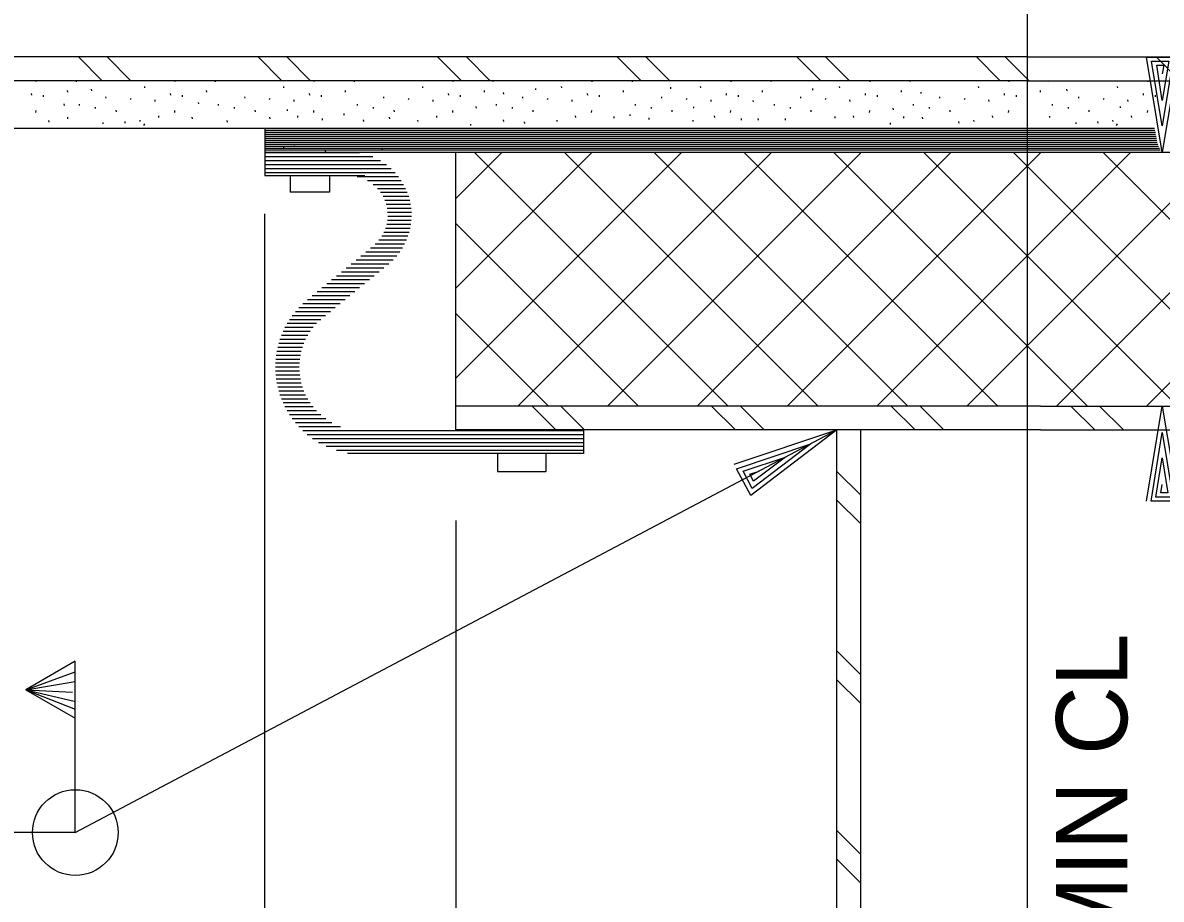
# Model space of a CAD drawing. Extents: x 22411.4 to 22495.4, y 22369.6 to 22415.
# Drawn here: x 22466.704 to 22469.692, y 22386.462 to 22388.762 of the extents above; entities that cross this region are included whole.
import ezdxf

# ---------------------------------------------------------------- set-up
doc = ezdxf.new("R2010")
doc.units = 0
for name, color, linetype in [('Level 1', 7, 'Continuous'), ('Level 10', 7, 'Continuous'), ('Level 2', 7, 'Continuous'), ('Level 4', 7, 'Continuous'), ('Level 8', 7, 'Continuous')]:
    doc.layers.add(name, color=color, linetype=linetype)

msp = doc.modelspace()

# ---------------------------------------------------------------- linework, layer by layer
at = {"layer": 'Level 1'}
for p, q in [((22469.3408, 22385.4019), (22469.3408, 22394.6266)), ((22467.4056, 22388.3603), (22467.4056, 22388.3173)), ((22467.5093, 22388.3603), (22467.5093, 22388.3173)), ((22467.5093, 22388.3173), (22467.4056, 22388.3173)), ((22467.3386, 22388.261), (22467.3386, 22385.4818)), ((22468.785, 22388.0689), (22468.785, 22388.0689)), ((22468.8753, 22387.6934), (22468.8753, 22387.6934)), ((22467.9496, 22387.6317), (22467.9496, 22387.5841)), ((22468.0771, 22387.6317), (22468.0771, 22387.5841)), ((22467.9496, 22387.5841), (22468.0771, 22387.5841)), ((22467.8408, 22387.4555), (22467.8408, 22385.4646))]:
    msp.add_line(p, q, dxfattribs=at)
for points in [[(22469.7359, 22388.6719), (22469.6946, 22388.4225), (22469.6533, 22388.6719), (22469.7239, 22388.6719), (22469.6946, 22388.4919), (22469.6666, 22388.6612), (22469.7119, 22388.6612), (22469.6946, 22388.5585), (22469.6799, 22388.6505), (22469.6986, 22388.6505), (22469.6946, 22388.6279)], [(22469.6533, 22387.5065), (22469.6946, 22387.7559), (22469.7359, 22387.5065), (22469.6653, 22387.5065), (22469.6946, 22387.6865), (22469.7226, 22387.5172), (22469.6773, 22387.5172), (22469.6946, 22387.6199), (22469.7093, 22387.5279), (22469.6906, 22387.5279), (22469.6946, 22387.5505)]]:
    msp.add_lwpolyline(points, dxfattribs=at)
at = {"layer": 'Level 10'}
for p, q in [((22466.8419, 22386.6366), (22468.8408, 22387.6934)), ((22468.8408, 22387.6934), (22468.8408, 22387.6934)), ((22468.7719, 22387.6569), (22468.7719, 22387.6569)), ((22466.8419, 22387.0866), (22466.7118, 22387.0116)), ((22466.8419, 22386.6366), (22466.8419, 22387.0866)), ((22466.7118, 22387.0116), (22466.8419, 22387.0584)), ((22466.7118, 22387.0116), (22466.8419, 22387.0329)), ((22466.7118, 22387.0116), (22466.8416, 22386.9366)), ((22466.7118, 22387.0116), (22466.8348, 22387.0051)), ((22466.7118, 22387.0116), (22466.8393, 22386.9819)), ((22466.7118, 22387.0116), (22466.8419, 22386.9609)), ((22466.8419, 22386.6366), (22465.3414, 22386.6366))]:
    msp.add_line(p, q, dxfattribs=at)
msp.add_lwpolyline([(22468.5711, 22387.6034), (22468.8408, 22387.6934), (22468.6146, 22387.5212), (22468.5774, 22387.5915), (22468.7719, 22387.6569), (22468.6182, 22387.54), (22468.5944, 22387.5851), (22468.7056, 22387.6219), (22468.6218, 22387.5589), (22468.612, 22387.5775), (22468.6366, 22387.5854)], dxfattribs=at)
msp.add_circle((22466.842, 22386.6365), 0.1125, dxfattribs=at)
at = {"layer": 'Level 2'}
for p, q in [((22469.3408, 22388.6725), (22464.1584, 22388.6725)), ((22469.3408, 22388.6725), (22474.5233, 22388.6725)), ((22469.3408, 22388.61), (22464.195, 22388.61)), ((22469.3408, 22388.61), (22474.4866, 22388.61)), ((22466.7276, 22388.572), (22466.7273, 22388.5761)), ((22466.7588, 22388.5679), (22466.7585, 22388.572)), ((22466.8219, 22388.5802), (22466.8216, 22388.5843)), ((22466.8849, 22388.5839), (22466.8846, 22388.5879)), ((22467.0244, 22388.591), (22467.0241, 22388.5951)), ((22467.0923, 22388.572), (22467.092, 22388.5761)), ((22467.1236, 22388.5679), (22467.1233, 22388.572)), ((22467.1867, 22388.5802), (22467.1863, 22388.5843)), ((22467.3892, 22388.591), (22467.3888, 22388.5951)), ((22467.4571, 22388.572), (22467.4568, 22388.5761)), ((22467.4883, 22388.5679), (22467.488, 22388.572)), ((22467.5514, 22388.5802), (22467.5511, 22388.5843)), ((22467.7539, 22388.591), (22467.7536, 22388.5951)), ((22467.8218, 22388.572), (22467.8215, 22388.5761)), ((22467.8531, 22388.5679), (22467.8528, 22388.572)), ((22467.9162, 22388.5802), (22467.9158, 22388.5843)), ((22467.9662, 22388.5747), (22467.9659, 22388.5788)), ((22468.0507, 22388.5857), (22468.0504, 22388.5898)), ((22468.1187, 22388.591), (22468.1183, 22388.5951)), ((22468.1866, 22388.572), (22468.1863, 22388.5761)), ((22468.2178, 22388.5679), (22468.2175, 22388.572)), ((22468.2809, 22388.5802), (22468.2806, 22388.5843)), ((22468.405, 22388.5891), (22468.4047, 22388.5932)), ((22468.4834, 22388.591), (22468.4831, 22388.5951)), ((22468.5513, 22388.572), (22468.551, 22388.5761)), ((22468.5826, 22388.5679), (22468.5823, 22388.572)), ((22468.6457, 22388.5802), (22468.6453, 22388.5843)), ((22468.7777, 22388.5854), (22468.7773, 22388.5895)), ((22468.8482, 22388.591), (22468.8478, 22388.5951)), ((22468.9161, 22388.572), (22468.9158, 22388.5761)), ((22468.9473, 22388.5679), (22468.947, 22388.572)), ((22469.0104, 22388.5802), (22469.0101, 22388.5843)), ((22469.0622, 22388.5763), (22469.0619, 22388.5803)), ((22469.2129, 22388.591), (22469.2126, 22388.5951)), ((22469.2808, 22388.572), (22469.2805, 22388.5761)), ((22469.3121, 22388.5679), (22469.3118, 22388.572)), ((22469.3752, 22388.5802), (22469.3748, 22388.5843)), ((22469.4447, 22388.5834), (22469.4444, 22388.5875)), ((22469.5777, 22388.591), (22469.5773, 22388.5951)), ((22469.6456, 22388.572), (22469.6453, 22388.5761)), ((22469.6768, 22388.5679), (22469.6765, 22388.572)), ((22466.8133, 22388.5453), (22466.813, 22388.5494)), ((22466.8532, 22388.5448), (22466.8528, 22388.5489)), ((22466.9225, 22388.5638), (22466.9222, 22388.5679)), ((22466.9871, 22388.5605), (22466.9889, 22388.5644)), ((22467.0516, 22388.5557), (22467.0513, 22388.5598)), ((22467.1658, 22388.549), (22467.1655, 22388.5531)), ((22467.2179, 22388.5448), (22467.2176, 22388.5489)), ((22467.2873, 22388.5638), (22467.2869, 22388.5679)), ((22467.3518, 22388.5605), (22467.3537, 22388.5644)), ((22467.4163, 22388.5557), (22467.416, 22388.5598)), ((22467.5827, 22388.5448), (22467.5823, 22388.5489)), ((22467.652, 22388.5638), (22467.6517, 22388.5679)), ((22467.7166, 22388.5605), (22467.7184, 22388.5644)), ((22467.7811, 22388.5557), (22467.7808, 22388.5598)), ((22467.8946, 22388.538), (22467.8943, 22388.542)), ((22467.9474, 22388.5448), (22467.9471, 22388.5489)), ((22468.0168, 22388.5638), (22468.0164, 22388.5679)), ((22468.0813, 22388.5605), (22468.0832, 22388.5644)), ((22468.1458, 22388.5557), (22468.1455, 22388.5598)), ((22468.3122, 22388.5448), (22468.3118, 22388.5489)), ((22468.3815, 22388.5638), (22468.3812, 22388.5679)), ((22468.4461, 22388.5605), (22468.4479, 22388.5644)), ((22468.4656, 22388.5377), (22468.4652, 22388.5418)), ((22468.5106, 22388.5557), (22468.5103, 22388.5598)), ((22468.6216, 22388.5542), (22468.6213, 22388.5583)), ((22468.6769, 22388.5448), (22468.6766, 22388.5489)), ((22468.7463, 22388.5638), (22468.7459, 22388.5679)), ((22468.8108, 22388.5605), (22468.8127, 22388.5644)), ((22468.8753, 22388.5557), (22468.875, 22388.5598)), ((22469.0417, 22388.5448), (22469.0413, 22388.5489)), ((22469.111, 22388.5638), (22469.1107, 22388.5679)), ((22469.1756, 22388.5605), (22469.1774, 22388.5644)), ((22469.2401, 22388.5557), (22469.2398, 22388.5598)), ((22469.4064, 22388.5448), (22469.4061, 22388.5489)), ((22469.4758, 22388.5638), (22469.4754, 22388.5679)), ((22469.5403, 22388.5605), (22469.5422, 22388.5644)), ((22469.5849, 22388.5386), (22469.5846, 22388.5427)), ((22469.6048, 22388.5557), (22469.6045, 22388.5598)), ((22466.738, 22388.5269), (22466.7388, 22388.5318)), ((22466.8225, 22388.5104), (22466.8222, 22388.5145)), ((22466.8953, 22388.5367), (22466.895, 22388.5408)), ((22466.9497, 22388.5285), (22466.9493, 22388.5326)), ((22467.0611, 22388.5136), (22467.0608, 22388.5177)), ((22467.1028, 22388.5269), (22467.1035, 22388.5318)), ((22467.1493, 22388.5104), (22467.1489, 22388.5145)), ((22467.2601, 22388.5367), (22467.2598, 22388.5408)), ((22467.3144, 22388.5285), (22467.3141, 22388.5326)), ((22467.3531, 22388.5104), (22467.3527, 22388.5145)), ((22467.399, 22388.5306), (22467.3986, 22388.5347)), ((22467.4258, 22388.5136), (22467.4255, 22388.5177)), ((22467.4675, 22388.5269), (22467.4683, 22388.5318)), ((22467.5477, 22388.5196), (22467.5473, 22388.5237)), ((22467.6248, 22388.5367), (22467.6245, 22388.5408)), ((22467.667, 22388.5104), (22467.6667, 22388.5145)), ((22467.6792, 22388.5285), (22467.6788, 22388.5326)), ((22467.7906, 22388.5136), (22467.7903, 22388.5177)), ((22467.8323, 22388.5269), (22467.833, 22388.5318)), ((22467.9896, 22388.5367), (22467.9893, 22388.5408)), ((22468.0439, 22388.5285), (22468.0436, 22388.5326)), ((22468.1553, 22388.5136), (22468.155, 22388.5177)), ((22468.197, 22388.5269), (22468.1978, 22388.5318)), ((22468.2563, 22388.512), (22468.256, 22388.5161)), ((22468.2985, 22388.5175), (22468.2982, 22388.5216)), ((22468.3481, 22388.5083), (22468.3478, 22388.5124)), ((22468.3543, 22388.5367), (22468.354, 22388.5408)), ((22468.4087, 22388.5285), (22468.4083, 22388.5326)), ((22468.5201, 22388.5136), (22468.5198, 22388.5177)), ((22468.5618, 22388.5269), (22468.5625, 22388.5318)), ((22468.7191, 22388.5367), (22468.7188, 22388.5408)), ((22468.7734, 22388.5285), (22468.7731, 22388.5326)), ((22468.8364, 22388.512), (22468.8361, 22388.5161)), ((22468.8848, 22388.5136), (22468.8845, 22388.5177)), ((22468.9265, 22388.5269), (22468.9273, 22388.5318)), ((22468.9888, 22388.534), (22468.9885, 22388.5381)), ((22469.0163, 22388.512), (22469.016, 22388.5161)), ((22469.0659, 22388.5102), (22469.0656, 22388.5142)), ((22469.0838, 22388.5367), (22469.0835, 22388.5408)), ((22469.1382, 22388.5285), (22469.1378, 22388.5326)), ((22469.2496, 22388.5136), (22469.2493, 22388.5177)), ((22469.2913, 22388.5269), (22469.292, 22388.5318)), ((22469.3999, 22388.5133), (22469.3996, 22388.5174)), ((22469.4486, 22388.5367), (22469.4483, 22388.5408)), ((22469.5029, 22388.5285), (22469.5026, 22388.5326)), ((22469.6143, 22388.5136), (22469.614, 22388.5177)), ((22469.656, 22388.5269), (22469.6568, 22388.5318)), ((22469.6744, 22388.485), (22466.1883, 22388.485)), ((22466.7729, 22388.5012), (22466.7726, 22388.5053)), ((22466.9151, 22388.4965), (22466.9154, 22388.5002)), ((22466.9728, 22388.4986), (22466.9724, 22388.5027)), ((22467.0122, 22388.5027), (22467.0118, 22388.5068)), ((22467.0215, 22388.4923), (22467.024, 22388.4965)), ((22467.2411, 22388.5012), (22467.2407, 22388.5053)), ((22467.3396, 22388.485), (22467.3396, 22388.3603)), ((22467.4908, 22388.5068), (22467.4904, 22388.5108)), ((22467.5991, 22388.5031), (22467.5987, 22388.5072)), ((22467.7417, 22388.5027), (22467.7413, 22388.5068)), ((22467.8799, 22388.4921), (22467.8796, 22388.4961)), ((22467.9662, 22388.5031), (22467.9659, 22388.5072)), ((22468.0213, 22388.4976), (22468.021, 22388.5017)), ((22468.1064, 22388.5027), (22468.1061, 22388.5068)), ((22468.4637, 22388.5028), (22468.4634, 22388.5069)), ((22468.5904, 22388.5065), (22468.5901, 22388.5106)), ((22468.6345, 22388.5065), (22468.6341, 22388.5106)), ((22468.7061, 22388.5065), (22468.7057, 22388.5106)), ((22468.9814, 22388.4955), (22468.9811, 22388.4996)), ((22469.1613, 22388.4986), (22469.1609, 22388.5027)), ((22469.2007, 22388.5027), (22469.2003, 22388.5068)), ((22469.4683, 22388.4965), (22469.4687, 22388.5002)), ((22469.526, 22388.4986), (22469.5257, 22388.5027)), ((22469.5654, 22388.5027), (22469.5651, 22388.5068)), ((22469.5748, 22388.4923), (22469.5773, 22388.4965)), ((22467.3386, 22388.4803), (22469.6752, 22388.4803)), ((22467.3386, 22388.4751), (22469.6764, 22388.4751)), ((22467.3386, 22388.4699), (22469.6764, 22388.4699)), ((22467.3386, 22388.4647), (22469.6786, 22388.4647)), ((22467.3386, 22388.4595), (22469.6794, 22388.4595)), ((22467.3386, 22388.4542), (22469.68, 22388.4542)), ((22467.3386, 22388.449), (22469.681, 22388.449)), ((22467.3386, 22388.4438), (22469.6829, 22388.4438)), ((22467.3386, 22388.4386), (22469.685, 22388.4386)), ((22467.3386, 22388.4334), (22469.6875, 22388.4334)), ((22467.3386, 22388.4282), (22469.6891, 22388.4282)), ((22467.3386, 22388.4225), (22471.3408, 22388.4225)), ((22467.3896, 22388.434), (22467.3893, 22388.4377)), ((22467.4164, 22388.4446), (22467.4167, 22388.4405)), ((22467.4979, 22388.4269), (22467.4983, 22388.4228)), ((22467.6479, 22388.4298), (22467.6454, 22388.434)), ((22467.8408, 22387.6903), (22467.8408, 22388.4225)), ((22467.6019, 22388.3603), (22467.3396, 22388.3603)), ((22469.3753, 22387.7559), (22467.8408, 22387.7559)), ((22469.3753, 22387.7559), (22470.8408, 22387.7559)), ((22469.3753, 22387.6934), (22467.8408, 22387.6934)), ((22468.1754, 22387.6934), (22468.1754, 22387.6317)), ((22468.8408, 22384.708), (22468.8408, 22387.6934)), ((22468.9033, 22384.708), (22468.9033, 22387.6934)), ((22469.3753, 22387.6934), (22470.8408, 22387.6934)), ((22468.1754, 22387.6317), (22467.556, 22387.6317))]:
    msp.add_line(p, q, dxfattribs=at)
for points in [[(22466.7398, 22388.6073), (22466.7396, 22388.61)], [(22466.845, 22388.6073), (22466.8448, 22388.61)], [(22466.9428, 22388.6087), (22466.9427, 22388.61)], [(22467.1046, 22388.6073), (22467.1044, 22388.61)], [(22467.2098, 22388.6073), (22467.2095, 22388.61)], [(22467.3076, 22388.6087), (22467.3075, 22388.61)], [(22467.4693, 22388.6073), (22467.4691, 22388.61)], [(22467.5745, 22388.6073), (22467.5743, 22388.61)], [(22467.6723, 22388.6087), (22467.6722, 22388.61)], [(22467.8341, 22388.6073), (22467.8339, 22388.61)], [(22467.9393, 22388.6073), (22467.939, 22388.61)], [(22468.0371, 22388.6087), (22468.037, 22388.61)], [(22468.1988, 22388.6073), (22468.1986, 22388.61)], [(22468.304, 22388.6073), (22468.3038, 22388.61)], [(22468.4018, 22388.6087), (22468.4017, 22388.61)], [(22468.5636, 22388.6073), (22468.5634, 22388.61)], [(22468.6688, 22388.6073), (22468.6685, 22388.61)], [(22468.7666, 22388.6087), (22468.7665, 22388.61)], [(22468.9283, 22388.6073), (22468.9281, 22388.61)], [(22469.0335, 22388.6073), (22469.0333, 22388.61)], [(22469.1313, 22388.6087), (22469.1312, 22388.61)], [(22469.2931, 22388.6073), (22469.2929, 22388.61)], [(22469.3983, 22388.6073), (22469.398, 22388.61)], [(22469.4961, 22388.6087), (22469.496, 22388.61)], [(22469.6578, 22388.6073), (22469.6576, 22388.61)], [(22467.5882, 22388.4203), (22467.3408, 22388.4203)], [(22467.6228, 22388.4099), (22467.3408, 22388.4099)], [(22467.6433, 22388.3995), (22467.3408, 22388.3995)], [(22467.6587, 22388.3891), (22467.3408, 22388.3891)], [(22467.6711, 22388.3787), (22467.3408, 22388.3787)], [(22467.6813, 22388.3683), (22467.3408, 22388.3683)], [(22467.69, 22388.3578), (22467.5818, 22388.3578)], [(22467.6974, 22388.3474), (22467.6085, 22388.3474)], [(22467.7036, 22388.337), (22467.6238, 22388.337)], [(22467.7089, 22388.3266), (22467.6348, 22388.3266)], [(22467.7133, 22388.3162), (22467.6431, 22388.3162)], [(22467.7169, 22388.3058), (22467.6495, 22388.3058)], [(22467.7197, 22388.2953), (22467.6544, 22388.2953)], [(22467.7219, 22388.2849), (22467.6579, 22388.2849)], [(22467.7234, 22388.2745), (22467.6603, 22388.2745)], [(22467.7238, 22388.2433), (22467.661, 22388.2433)], [(22467.7242, 22388.2641), (22467.6616, 22388.2641)], [(22467.7243, 22388.2537), (22467.6618, 22388.2537)], [(22467.7208, 22388.2224), (22467.6561, 22388.2224)], [(22467.7226, 22388.2328), (22467.6591, 22388.2328)], [(22467.711, 22388.1912), (22467.6388, 22388.1912)], [(22467.715, 22388.2016), (22467.6462, 22388.2016)], [(22467.7183, 22388.212), (22467.6519, 22388.212)], [(22467.6935, 22388.1599), (22467.6041, 22388.1599)], [(22467.7003, 22388.1703), (22467.6168, 22388.1703)], [(22467.7061, 22388.1808), (22467.6292, 22388.1808)], [(22467.6646, 22388.1287), (22467.5658, 22388.1287)], [(22467.676, 22388.1391), (22467.5786, 22388.1391)], [(22467.6854, 22388.1495), (22467.5913, 22388.1495)], [(22467.6264, 22388.0974), (22467.5275, 22388.0974)], [(22467.6391, 22388.1078), (22467.5403, 22388.1078)], [(22467.6519, 22388.1183), (22467.553, 22388.1183)], [(22467.5881, 22388.0662), (22467.4892, 22388.0662)], [(22467.6008, 22388.0766), (22467.502, 22388.0766)], [(22467.6136, 22388.087), (22467.5147, 22388.087)], [(22467.5498, 22388.0349), (22467.4509, 22388.0349)], [(22467.5625, 22388.0453), (22467.4637, 22388.0453)], [(22467.5753, 22388.0558), (22467.4764, 22388.0558)], [(22467.5114, 22388.0037), (22467.4196, 22388.0037)], [(22467.5242, 22388.0141), (22467.4287, 22388.0141)], [(22467.537, 22388.0245), (22467.4391, 22388.0245)], [(22467.4861, 22387.9828), (22467.4042, 22387.9828)], [(22467.4987, 22387.9933), (22467.4114, 22387.9933)], [(22467.4585, 22387.9516), (22467.3872, 22387.9516)], [(22467.4662, 22387.962), (22467.3922, 22387.962)], [(22467.4753, 22387.9724), (22467.3978, 22387.9724)], [(22467.4418, 22387.9203), (22467.3758, 22387.9203)], [(22467.4464, 22387.9308), (22467.379, 22387.9308)], [(22467.452, 22387.9412), (22467.3828, 22387.9412)], [(22467.4326, 22387.8891), (22467.3692, 22387.8891)], [(22467.4349, 22387.8995), (22467.3709, 22387.8995)], [(22467.438, 22387.9099), (22467.3731, 22387.9099)], [(22467.4296, 22387.8578), (22467.3671, 22387.8578)], [(22467.4299, 22387.8683), (22467.3673, 22387.8683)], [(22467.4309, 22387.8787), (22467.368, 22387.8787)], [(22467.4299, 22387.8474), (22467.3673, 22387.8474)], [(22467.4309, 22387.837), (22467.368, 22387.837)], [(22467.4325, 22387.8266), (22467.3692, 22387.8266)], [(22467.4349, 22387.8162), (22467.3709, 22387.8162)], [(22467.4379, 22387.8058), (22467.3731, 22387.8058)], [(22467.4417, 22387.7953), (22467.3758, 22387.7953)], [(22467.4463, 22387.7849), (22467.379, 22387.7849)], [(22467.4519, 22387.7745), (22467.3827, 22387.7745)], [(22467.4584, 22387.7641), (22467.3871, 22387.7641)], [(22467.4661, 22387.7537), (22467.3921, 22387.7537)], [(22467.4751, 22387.7433), (22467.3977, 22387.7433)], [(22467.4859, 22387.7328), (22467.4041, 22387.7328)], [(22467.499, 22387.7224), (22467.4113, 22387.7224)], [(22467.5154, 22387.712), (22467.4194, 22387.712)], [(22467.538, 22387.7016), (22467.4285, 22387.7016)], [(22468.1742, 22387.6912), (22467.4389, 22387.6912)], [(22468.1742, 22387.6808), (22467.4507, 22387.6808)], [(22468.1742, 22387.6703), (22467.4643, 22387.6703)], [(22468.1742, 22387.6599), (22467.4806, 22387.6599)], [(22468.1742, 22387.6495), (22467.5006, 22387.6495)], [(22468.1742, 22387.6391), (22467.5277, 22387.6391)]]:
    msp.add_lwpolyline(points, dxfattribs=at)
at = {"layer": 'Level 8'}
for points in [[(22466.9125, 22388.61), (22466.85, 22388.6725)], [(22466.9879, 22388.61), (22466.9254, 22388.6725)], [(22467.3839, 22388.61), (22467.3214, 22388.6725)], [(22467.4593, 22388.61), (22467.3968, 22388.6725)], [(22467.8553, 22388.61), (22467.7928, 22388.6725)], [(22467.9307, 22388.61), (22467.8682, 22388.6725)], [(22468.3267, 22388.61), (22468.2642, 22388.6725)], [(22468.4021, 22388.61), (22468.3396, 22388.6725)], [(22468.7981, 22388.61), (22468.7356, 22388.6725)], [(22468.8735, 22388.61), (22468.811, 22388.6725)], [(22469.2695, 22388.61), (22469.207, 22388.6725)], [(22469.3449, 22388.61), (22469.2824, 22388.6725)], [(22469.7409, 22388.61), (22469.6784, 22388.6725)], [(22467.8408, 22387.8296), (22468.4338, 22388.4226)], [(22467.8408, 22388.0653), (22468.1981, 22388.4226)], [(22467.8408, 22388.301), (22467.9624, 22388.4225)], [(22468.5557, 22387.7559), (22467.889, 22388.4225)], [(22468.0029, 22387.7559), (22468.6695, 22388.4226)], [(22468.7914, 22387.7559), (22468.1247, 22388.4225)], [(22468.2386, 22387.7559), (22468.9052, 22388.4225)], [(22469.0271, 22387.7559), (22468.3604, 22388.4225)], [(22468.4743, 22387.7559), (22469.1409, 22388.4225)], [(22469.2628, 22387.7559), (22468.5961, 22388.4225)], [(22468.7099, 22387.7559), (22469.3766, 22388.4225)], [(22469.4985, 22387.7559), (22468.8318, 22388.4225)], [(22468.9457, 22387.7559), (22469.6123, 22388.4225)], [(22469.7342, 22387.7559), (22469.0675, 22388.4225)], [(22469.1813, 22387.7559), (22469.848, 22388.4225)], [(22469.9699, 22387.7559), (22469.3032, 22388.4225)], [(22469.417, 22387.7559), (22470.0837, 22388.4225)], [(22470.2056, 22387.7559), (22469.5389, 22388.4226)], [(22469.6528, 22387.7559), (22470.3194, 22388.4225)], [(22468.3199, 22387.7559), (22467.8408, 22388.235)], [(22468.0842, 22387.7559), (22467.8408, 22387.9993)], [(22468.103, 22387.6934), (22468.0405, 22387.7559)], [(22468.1785, 22387.6934), (22468.116, 22387.7559)], [(22468.5744, 22387.6934), (22468.5119, 22387.7559)], [(22468.6499, 22387.6934), (22468.5874, 22387.7559)], [(22469.0459, 22387.6934), (22468.9833, 22387.7559)], [(22469.1213, 22387.6934), (22469.0588, 22387.7559)], [(22469.5173, 22387.6934), (22469.4548, 22387.7559)], [(22469.5927, 22387.6934), (22469.5302, 22387.7559)], [(22468.9033, 22387.5222), (22468.8408, 22387.5847)], [(22468.9033, 22387.4468), (22468.8408, 22387.5093)], [(22468.9033, 22387.0508), (22468.8408, 22387.1133)], [(22468.9033, 22386.9754), (22468.8408, 22387.0379)], [(22468.9033, 22386.5794), (22468.8408, 22386.6419)], [(22468.9033, 22386.504), (22468.8408, 22386.5665)]]:
    msp.add_lwpolyline(points, dxfattribs=at)

# ---------------------------------------------------------------- texts
at = {"layer": 'Level 4'}
msp.add_text("7'' MIN CL", height=0.18667, rotation=90, dxfattribs=at).set_placement((22469.6026, 22386.0098))

doc.saveas('drawing.dxf')
